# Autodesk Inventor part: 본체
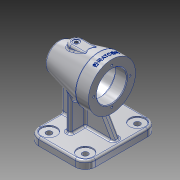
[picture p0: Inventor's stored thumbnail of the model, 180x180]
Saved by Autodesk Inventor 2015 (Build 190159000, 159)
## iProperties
Created: 2024-12
Part Number: 본체
Material: 알루미늄 6061
Document SubType Name: Modeling
Designer: 102-5
Density: 2.7 g/cm^3
Appearance: 알루미늄 - 평지
Mass: 739.322 g
Surface Area: 673.876 cm^2
Volume: 273.823 cm^3
Author: 102-5
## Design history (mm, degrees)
sketch "스케치1"
  geometry: C1 r 37 at (0, 0); 1 further point
  constraints: 1 centre point, 1 coincident
  dimensions: "d0" = 74 diameter of C1
extrude "돌출1" new body sketch "스케치1" distance "d1" = 20; taper "d2" = 0 deg
node "작업 평면1"
sketch "스케치2"
  geometry: C1 r 37 at (0, 0) reference
sketch "스케치3"
  geometry: C1 r 21 at (0, 0); 1 further point
  constraints: 1 centre point, 1 coincident
  dimensions: "d4" = 42 diameter of C1
feature "로프트1" sketch "스케치3" dims "d5" = 0, "d6" = 90 deg, "d7" = 0, "d8" = 90 deg
  node "모서리1"
node "작업 평면2"
sketch "스케치4"
  geometry: L1 (-74, -57)-(15, -57); L2 (15, -57)-(15, 57); L3 (15, 57)-(-74, 57); L4 (-74, 57)-(-74, -57); L5 (0, 37)-(0, -37) reference; 3 further points
  constraints: 8 end point, 2 midpoint, 2 parallel, 1 horizontal, 1 horizontal alignment, 1 perpendicular
  dimensions: "d10" = 15 distance from line of L2.end L5; "d11" = 114 distance between parallel lines of L3 L1; "d12" = 89 distance between parallel lines of L2 L4
extrude "돌출2" join sketch "스케치4" distance "d13" = 12; taper "d14" = 0 deg
sketch "스케치5"
  geometry: L1 (15, -57)-(15, 57) reference; L2 (-74, 57)-(-74, -57) reference; L3 (8, -5)-(-74, -5); L4 (-74, -5)-(-74, 5); L5 (-74, 5)-(8, 5); L6 (8, 5)-(8, -5); L7 (8, -5)-(-74, 5); L8 (-74, -5)-(8, 5); L9 (-37, -28)-(-45, -28); L10 (-45, -28)-(-45, 28); L11 (-45, 28)-(-37, 28); L12 (-37, 28)-(-37, -28); L13 (-37, -28)-(-45, 28); L14 (-45, -28)-(-37, 28); 5 further points
  constraints: 24 end point, 6 midpoint, 4 parallel, 2 horizontal, 2 horizontal alignment, 2 perpendicular, 1 point on line
  dimensions: "d15" = 10 distance between parallel lines of L5 L3; "d16" = 8 distance between parallel lines of L12 L10; "d17" = 29 distance between parallel lines of L10 L2; "d18" = 56 distance between parallel lines of L11 L9; "d19" = 7 distance between parallel lines of L1 L6
extrude "돌출3" join sketch "스케치5" distance "d20" = 70; taper "d21" = 0 deg
feature "면 기울기1" dims angle "d22" = 30 deg
fillet "모깎기1" dims "d23" = 16
sketch "스케치7"
  geometry: A1 r 16 centre (-1, -41) between (-1, -57) and (15, -41) reference; 1 further point
hole "구멍1" sketch "스케치7" at (-1, -41) diameter "d24" = 9; stored, may be unused: countersink angle "d28" = 90 deg, drill point angle "d30" = 118 deg; dims "d25" = 6, "d26" = 24, "d27" = 2, "d29" = 8
sketch "스케치8"
  geometry: A1 r 16 centre (-58, -41) between (-74, -41) and (-58, -57) reference; 1 further point
hole "구멍2" sketch "스케치8" at (-58, -41) diameter "d31" = 9; stored, may be unused: countersink angle "d35" = 90 deg, drill point angle "d37" = 118 deg; dims "d32" = 6, "d33" = 24, "d34" = 2, "d36" = 8
sketch "스케치10"
  geometry: L1 (20, 37)-(84, 21) reference; L2 (18, 32.346)-(63, 21.096); L3 (18, 32.346)-(18, 0); L4 (18, 0)-(63, 0); L5 (0, -37)-(0, 37) reference; L6 (63, 21.096)-(63, 0); 2 further points
  constraints: 8 end point, 2 vertical, 1 horizontal alignment, 1 midpoint, 1 parallel, 1 perpendicular
  dimensions: "d38" = 5 distance between parallel lines of L1 L2; "d39" = 18 distance between parallel lines of L3 L5; "d41" = 45 distance between parallel lines of L6 L3
revolve "회전1" sketch "스케치10" stored, may be unused: angle "d42" = 90 deg
sketch "스케치11"
  geometry: C1 r 37 at (0, 0) reference; C2 r 23.5 at (0, 0)
  constraints: 1 centre point, 1 coincident
  dimensions: "d43" = 47 diameter of C2
extrude "돌출4" cut sketch "스케치11" distance "d44" = 18; taper "d45" = 0 deg
sketch "스케치12"
  geometry: C1 r 21.096 at (0, 0) reference; C2 r 17.5 at (0, 0)
  constraints: 1 centre point, 1 coincident
  dimensions: "d46" = 35 diameter of C2
extrude "돌출5" cut sketch "스케치12" distance "d47" = 10; taper "d48" = 0 deg
sketch "스케치13"
  geometry: C1 r 17.5 at (0, 0) reference; C2 r 15.5 at (0, 0)
  constraints: 1 centre point, 1 coincident
  dimensions: "d49" = 31 diameter of C2
extrude "돌출6" cut sketch "스케치13" distance "d50" = 3; taper "d51" = 0 deg
sketch "스케치14"
  geometry: L1 (0, 0)-(-28.5, 0); C1 r 37 at (0, 0) reference
  constraints: 2 end point, 1 horizontal
  dimensions: "d52" = 28.5 distance of L1.start L1.end
hole "구멍3" sketch "스케치14" at (-28.5, 0) diameter "d53" = 3.242; stored, may be unused: countersink angle "d57" = 90 deg, drill point angle "d59" = 118 deg; dims "d54" = 8, "d55" = 24, "d56" = 2, "d58" = 10
node "작업 평면3"
sketch "스케치15"
  geometry: L1 (56, 0)-(26, 0); L2 (56, -10)-(26, -10); L3 (26, 10)-(56, 10); L4 (0, -37)-(0, 37) reference; A1 r 10 centre (56, 0) between (56, -10) and (56, 10); A2 r 10 centre (26, 0) between (26, 10) and (26, -10); 2 further points
  constraints: 8 end point, 4 point on circle, 4 tangent, 2 centre point, 2 horizontal alignment, 1 horizontal, 1 midpoint, 1 parallel
  dimensions: "d64" = 56 distance from line of L4 L1.start; "d65" = 20 distance between parallel lines of L2 L3; "d66" = 30 distance of L1.start L1.end
extrude "돌출7" join sketch "스케치15" distance "d67" = 30; taper "d68" = 0 deg
sketch "스케치16"
  geometry: L1 (0, 0)-(73, 0); L2 (63, -17.5)-(63, 15.977) reference; L3 (63, 19.851)-(63, -21.096) reference; L4 (63, -21.096)-(18, -32.346) reference; L5 (18, 31.785)-(18, -32.346) reference; L6 (0, -23.5)-(18, -23.5) reference; L7 (0, -23.5)-(0, 23.5) reference; L8 (63, -17.5)-(73, -17.5) reference; L9 (73, -15.5)-(73, 15.5) reference; L10 (73, -17.5)-(73, 17.5) reference
  constraints: 2 end point, 1 horizontal, 1 midpoint
revolve "회전2" sketch "스케치16" stored, may be unused: angle "d69" = 90 deg
sketch "스케치17"
  geometry: A1 r 10 centre (-56, 0) between (-56, 10) and (-56, -10) reference; 1 further point
hole "구멍4" sketch "스케치17" at (-56, 0) diameter "d70" = 5.188; stored, may be unused: countersink angle "d74" = 90 deg, drill point angle "d76" = 118 deg; dims "d71" = 12, "d72" = 10, "d73" = 1, "d75" = 16
fillet "모깎기2" dims "d77" = 5
fillet "모깎기3" dims "d78" = 3
fillet "모깎기4" dims "d79" = 0.3
chamfer "모따기1" distance "d80" = 1; stored, may be unused: second distance "d81" = 2, angle "d82" = 45 deg
fillet "모깎기5" dims "d83" = 3
fillet "모깎기6" dims "d84" = 3
fillet "모깎기7" dims "d85" = 3
fillet "모깎기8" dims "d86" = 3
fillet "모깎기9" dims "d87" = 3
node "작업 평면4"
sketch "스케치18"
  geometry: L1 (0, 37)-(0, -37) reference; 3 further points
  constraints: 1 horizontal alignment, 1 midpoint, 1 other
  dimensions: "d89" = 9 distance from line of point (-9, 0) L1
feature "엠보싱1" sketch "스케치18" dims "d0" = 74, "d90" = 0.5, "d91" = 0
node "솔리드1"
mirror "대칭1"
mirror "대칭2"
pattern_circular "원형 패턴1" dims angle "d61" = 360 deg
other parameters: "d3" = 64, "d9" = -82, "d40" = 45, "d63" = -115, "d88" = 148.75
